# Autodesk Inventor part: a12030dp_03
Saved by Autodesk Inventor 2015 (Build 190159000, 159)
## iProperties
Created: 2022-06
Part Number: a12030dp_03
Checked By: TraceParts S.A.
Material: Générique
Catalog Web Link: www.traceparts.com
Document SubType Name: Modeling
Designer: TraceParts
Density: 1 g/cm^3
Appearance: Par défaut
Company: TraceParts S.A.
Author: TraceParts
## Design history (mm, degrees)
feature "a12030dp_03.ipt"
node "Solide1"
